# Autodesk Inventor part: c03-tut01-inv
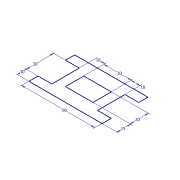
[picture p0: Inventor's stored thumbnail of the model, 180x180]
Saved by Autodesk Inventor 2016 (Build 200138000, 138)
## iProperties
Created: 2010-01
Part Number: c03-tut01-inv
Document SubType Name: Modeling
Designer: CADSoft
Density: 1 g/cm^3
Material: Generic
Appearance: Default
Author: CADSoft
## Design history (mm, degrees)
sketch "Sketch1"
  geometry: L1 (80, 0)-(0, 0); L2 (0, 0)-(0, 10); L3 (0, 10)-(15, 10); L4 (15, 10)-(15, 40); L5 (15, 40)-(0, 40); L6 (0, 40)-(0, 50); L7 (0, 50)-(80, 50); L8 (80, 50)-(80, 40); L9 (80, 40)-(65, 40); L10 (65, 40)-(65, 10); L11 (65, 10)-(80, 10); L12 (80, 10)-(80, 0); L13 (25, 35)-(55, 35); L14 (55, 35)-(55, 15); L15 (55, 15)-(25, 15); L16 (25, 15)-(25, 35); 2 further points
  constraints: 32 end point, 9 equal length, 7 horizontal, 6 vertical, 2 coincident, 1 other
  dimensions: "d1" = 80 distance of L1.start L1.end; "d2" = 10 distance of L1.end L2.end; "d3" = 30 distance of L3.end L4.end; "d4" = 20 distance of L13.end L14.end; "d5" = 30 distance of L13.start L13.end; "d6" = 10 distance between parallel lines of L16 L4; "d7" = 10 distance between parallel lines of L10 L14; "d8" = 15 distance between parallel lines of L15 L1
